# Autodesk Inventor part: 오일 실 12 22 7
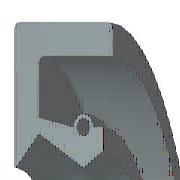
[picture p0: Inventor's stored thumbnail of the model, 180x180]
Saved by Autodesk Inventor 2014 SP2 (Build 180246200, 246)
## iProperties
Created: 2012-02
Part Number: 오일 실 12 22 7
Material: 고무
Description: 오일-실
Document SubType Name: Modeling
Standard: KS B 2804
Designer: mduedu
Standards Organization: KS
Language: ko-KR
Size Designation: D - 12 22 7
Categories: <MemberInstance><Categories><Category DisplayName="샤프트 부품" InternalName="7f7aeb1f-a693-4053-b835-cee3144e0d98" Mnemonic="SHFT"><Category DisplayName="실링" Intern
Density: 0.93 g/cm^3
Mass: 1.25383 g
Surface Area: 18.4996 cm^2
Volume: 1.3482 cm^3
Appearance: 고무 - 검은색 - 버전 1.1
IsCustomPart: 1
Author: mduedu
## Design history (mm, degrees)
revolve "본체" stored, may be unused: angle "d17" = 90 deg
revolve "스프링1" stored, may be unused: angle "d18" = 90 deg
body "Solid1"
sketch "스케치1"
  geometry: L1 (0, 11)-(7, 11); L2 (7, 9.25)-(1.75, 9.25); L3 (1.75, 7.75)-(4.9, 6); L4 (4.9, 6)-(0, 6); L5 (0, 0)-(9.586, 0) reference; L6 (4.9, 6)-(6.3, 6.875); L7 (0, 18)-(0, -3) reference; L8 (-1.941, 0)-(11.507, 0) reference; L9 (4.2, 8.1)-(1.75, 8.59); L10 (1.75, 8.59)-(1.75, 9.25); L11 (0, 11)-(0, 6.088); L12 (4.9, 6)-(0, 6); L13 (1.75, 7.75)-(0.152, 6.028); L14 (7, 11)-(7, 9.25); L15 (5.6, 8.1)-(6.3, 8.1); L16 (6.3, 8.1)-(6.3, 6.875); C1 r 0.455 at (4.9, 8.1); A1 r 0.7 centre (4.9, 8.1) between (5.6, 8.1) and (4.2, 8.1); A2 r 0.088 centre (0.088, 6.088) between (0, 6.088) and (0.152, 6.028); 1 further point
  constraints: 28 end point, 5 horizontal alignment, 5 point on line, 4 point on circle, 4 vertical alignment, 3 centre point, 3 tangent, 2 collinear, 2 horizontal, 2 perpendicular, 1 coincident, 1 parallel
  dimensions: "d0" = 22 diameter of L1 L5 (= SD2); "d1" = 1.75 distance of L1.end L2.start (= SD); "d2" = 0.91 diameter of C1 (= SPDI); "d3" = 1.4 diameter of A1 (= SPDA); "d4" = 12 diameter of L3.end L5 (= NND); "d5" = 15.5 diameter of L3.start L5 (= TKDM); "d7" = 17.18 diameter of L9.end L5 (= TKDM + 0.24 x SWDT); "d8" = 1.75 distance between parallel lines of L11 L10 (= SD); "d9" = 4.9 distance from line of L11 C1.centre (= SPDST); "d10" = 16.2 diameter of C1.centre L5 (= HLDM); "d11" = 0.0875 radius of A2 (= 0.25 x LAB); "d12" = 6.3 distance between parallel lines of L11 L16 (= SDI); "d13" = 13.75 diameter of L6.end L5 (= ABDM); "d14" = 7 distance from line of L11 L1.end (= SWDT)
fillet "모깎기1" dims "d6" = 0.3 (= RR)
other parameters: "SD2" = 22 [user parameter; used in 1 equation term], "SWDT" = 7 [user parameter; used in 2 equation terms], "RR" = 0.3 [user parameter; used in 1 equation term], "SD" = 1.75 [user parameter; used in 2 equation terms], "NND" = 12 [user parameter; used in 1 equation term], "SPDA" = 1.4 [user parameter; used in 1 equation term], "SPDI" = 0.91 [user parameter; used in 1 equation term], "TKDM" = 15.5 [user parameter; used in 2 equation terms], "HLDM" = 16.2 [user parameter; used in 1 equation term], "ABDM" = 13.75 [user parameter; used in 1 equation term], "SDI" = 6.3 [user parameter; used in 1 equation term], "SPDST" = 4.9 [user parameter; used in 1 equation term], "LAB" = 0.35 [user parameter; used in 1 equation term], "d15" = 0, "d16" = 0, "d19" = 0
